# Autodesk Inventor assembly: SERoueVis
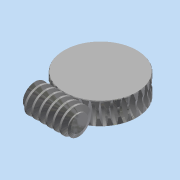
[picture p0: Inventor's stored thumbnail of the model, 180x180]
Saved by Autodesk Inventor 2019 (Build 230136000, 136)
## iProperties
Created: 2023-04
Part Number: SERoueVis
Material: Générique
Document SubType Name: Assembly
Designer: Thier
Author: Thier
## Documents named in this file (2)
- C:\Travail\PREPA\EC02\TP\TP3-Arbre\EC02-T03-Pieces-SEMoteur\SERoueVis.iam
- C:\Travail\PREPA\EC02\TP\TP3-Arbre\EC02-T03-Pieces-SEMoteur\SERoueVis\Design Accelerator\Engrenages à vis sans fin1.iam
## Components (1 placed, 1 different names)
1. Engrenages à vis sans fin:1 [sub-assembly]
